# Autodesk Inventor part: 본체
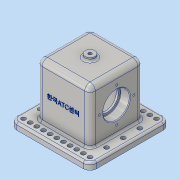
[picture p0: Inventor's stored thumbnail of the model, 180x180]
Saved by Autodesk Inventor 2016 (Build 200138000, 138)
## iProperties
Created: 2018-11
Part Number: 본체
Material: 알루미늄 6061
Document SubType Name: Modeling
Designer: 605-11
Density: 2.7 g/cm^3
Appearance: 알루미늄 - 평지
Mass: 1016.92 g
Surface Area: 777.15 cm^2
Volume: 376.637 cm^3
Author: 605-11
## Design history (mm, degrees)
sketch "스케치1"
  geometry: L1 (50, 60)-(-50, 60); L2 (-60, 50)-(-60, -50); L3 (-50, -60)-(50, -60); L4 (60, -50)-(60, 50); L5 (60, 60)-(-60, -60); L6 (-60, 60)-(60, -60); A1 r 10 centre (50, -50) between (50, -60) and (60, -50); A2 r 10 centre (-50, -50) between (-60, -50) and (-50, -60); A3 r 10 centre (-50, 50) between (-50, 60) and (-60, 50); A4 r 10 centre (50, 50) between (60, 50) and (50, 60); 1 further point
  constraints: 12 end point, 8 point on circle, 8 point on line, 8 tangent, 4 centre point, 3 equal radius, 2 midpoint, 2 parallel, 1 horizontal, 1 perpendicular
  dimensions: "d0" = 120 distance of L5.end L6.end; "d1" = 120 distance of L6.start L5.end; "d2" = 10 radius of A1
extrude "돌출1" new body sketch "스케치1" distance "d3" = 10; taper "d4" = 0 deg
sketch "스케치2"
  geometry: L1 (-40, -40)-(40, -40); L2 (40, -40)-(40, 40); L3 (40, 40)-(-40, 40); L4 (-40, 40)-(-40, -40); L5 (-40, -40)-(40, 40); L6 (40, -40)-(-40, 40); 1 further point
  constraints: 12 end point, 2 midpoint, 2 parallel, 1 horizontal, 1 perpendicular
  dimensions: "d5" = 80 distance of L2.end L3.end; "d6" = 80 distance of L1.end L2.end
extrude "돌출2" join sketch "스케치2" distance "d7" = 80; taper "d8" = 0 deg
sketch "스케치4"
  geometry: L1 (-23, 30)-(23, 30); L2 (23, 30)-(23, -30); L3 (23, -30)-(-23, -30); L4 (-23, -30)-(-23, 30); L5 (-23, 30)-(23, -30); L6 (23, 30)-(-23, -30); 1 further point
  constraints: 12 end point, 2 midpoint, 2 parallel, 1 horizontal, 1 perpendicular
  dimensions: "d9" = 46 distance of L2.end L3.end; "d10" = 60 distance of L1.end L2.end
extrude "돌출3" cut sketch "스케치4" distance "d11" = 80; taper "d12" = 0 deg
fillet "모깎기1" dims "d13" = 8
fillet "모깎기2" dims "d14" = 3
fillet "모깎기3" dims "d15" = 3
sketch "스케치7"
  geometry: L1 (82, -90)-(-18, -90) reference; L2 (-8, 0)-(-8, -77) reference; 2 further points
  dimensions: "d17" = 48 distance from line of L1 point (32, -42); "d18" = 40 distance from line of L2 point (32, -42)
hole "구멍1" sketch "스케치7" at (32, -42) diameter "d19" = 33; stored, may be unused: countersink angle "d23" = 90 deg, drill point angle "d25" = 0 deg; dims "d20" = 6, "d21" = 40, "d22" = 14, "d24" = 17
sketch "스케치9"
  geometry: C1 r 7.5 at (0, 0); 1 further point
  constraints: 1 centre point, 1 coincident
  dimensions: "d26" = 15 diameter of C1
extrude "돌출4" join sketch "스케치9" distance "d27" = 5; taper "d28" = 0 deg
fillet "모깎기4" dims "d29" = 3
sketch "스케치10"
  geometry: C1 r 7.5 at (0, 0) reference
hole "구멍2" sketch "스케치10" at (0, 0) diameter "d30" = 5.134; stored, may be unused: countersink angle "d34" = 90 deg, drill point angle "d36" = 0 deg; dims "d31" = 40, "d32" = 40, "d33" = 14, "d35" = 40
chamfer "모따기1" distance "d37" = 1; stored, may be unused: second distance "d38" = 2, angle "d39" = 45 deg
fillet "모깎기5" dims "d40" = 0.6
sketch "스케치11"
  geometry: C1 r 21 at (32, -42) reference; 2 further points
  constraints: 1 vertical alignment
  dimensions: "d41" = 26 distance of C1.centre point (32, -16)
hole "구멍3" sketch "스케치11" at (32, -16) diameter "d42" = 3.242; stored, may be unused: countersink angle "d46" = 90 deg, drill point angle "d48" = 118 deg; dims "d43" = 8, "d44" = 40, "d45" = 14, "d47" = 10
sketch "스케치12"
  geometry: L1 (50, 60)-(-50, 60) reference; L2 (-60, 50)-(-60, -50) reference; A1 r 10 centre (-50, 50) between (-50, 60) and (-60, 50) reference; A2 r 10 centre (50, 50) between (60, 50) and (50, 60) reference; 11 further points
  constraints: 8 horizontal alignment
  dimensions: "d53" = 10 distance of point (-30, 50) point (-40, 50); "d54" = 10 distance of point (-20, 50) point (-30, 50); "d56" = 10 distance of point (-10, 50) point (-20, 50); "d57" = 10 distance of point (0, 50) point (-10, 50); "d58" = 10 distance of point (10, 50) point (0, 50); "d59" = 10 distance of point (20, 50) point (10, 50); "d60" = 10 distance of point (30, 50) point (20, 50); "d64" = 10 distance from line of point (-50, 50) L2; "d65" = 10 distance from line of L1 point (-50, 50); "d66" = 10 distance of point (-40, 50) A1.centre; "d67" = 10 distance of point (40, 50) point (30, 50); "d68" = 10 distance of A2.centre point (40, 50)
hole "구멍4" sketch "스케치12" at (-40, 50), (-30, 50), (-20, 50), (-10, 50), (0, 50), (10, 50), (20, 50), (30, 50), (-50, 50), (40, 50), (50, 50) diameter "d69" = 6.6; stored, may be unused: countersink angle "d73" = 90 deg, drill point angle "d75" = 0 deg; dims "d70" = 6, "d71" = 4, "d72" = 2, "d74" = 8
sketch "스케치13"
  geometry: C1 r 3.3 at (-50, -50) reference; C2 r 3.3 at (-50, 50) reference; A1 r 10 centre (-50, 50) between (-50, 60) and (-60, 50) reference; 4 further points
  constraints: 2 vertical alignment
  dimensions: "d76" = 25 distance of point (-50, 25) A1.centre; "d77" = 25 distance of point (-50, 0) point (-50, 25); "d78" = 25 distance of point (-50, -25) point (-50, 0); "d79" = 25 distance of C1.centre point (-50, -25)
hole "구멍5" sketch "스케치13" at (-50, 25), (-50, 0), (-50, -25) diameter "d80" = 6.6; stored, may be unused: countersink angle "d84" = 90 deg, drill point angle "d86" = 0 deg; dims "d81" = 6, "d82" = 4, "d83" = 2, "d85" = 8
sketch "스케치14"
  geometry: L1 (82, -90)-(-18, -90) reference; L2 (-8, 0)-(-8, -77) reference; 2 further points
  constraints: 1 other
  dimensions: "d87" = 48 distance from line of L1 point (32, -42); "d88" = 40 distance from line of L2 point (32, -42)
feature "엠보싱1" sketch "스케치14" dims "d0" = 120, "d1" = 120, "d2" = 10, "d5" = 80, "d89" = 0.5, "d90" = 0
fillet "모깎기6" dims "d91" = 8
fillet "모깎기7" dims "d92" = 3
fillet "모깎기8" dims "d93" = 3
node "솔리드1"
mirror "대칭1"
pattern_circular "원형 패턴1" dims angle "d50" = 360 deg
mirror "대칭2"
mirror "대칭3"
mirror "대칭4"
